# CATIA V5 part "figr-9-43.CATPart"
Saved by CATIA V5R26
Part number: Part1
Bounding box of the stored display mesh (mm): x -60 to 60, y -70.327 to 65.87, z 0 to 125
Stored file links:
  D:\_Deepak\CATIA\CATIA V5-6R2016_Deepak\Resources\Part files\Partfiles\c09_catia_v5_6r2016_prt\figr-9-43.CATPart
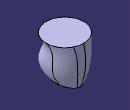
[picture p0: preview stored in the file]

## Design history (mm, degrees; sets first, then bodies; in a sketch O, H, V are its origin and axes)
Set1
  Plane1: type Offset, RefPlane xy-plane, Offset 125
Body1 (main body)
  Sketch1 on xy-plane, origin (0, 0, 0), H (1, 0, 0), V (0, 1, 0)
    ellipse A1 centre (0, 0) semi-axes 50, 30 rotation 270
    point P1 (30, 0)
    coincidence: P1 H, A1 P1
  Sketch2 on Plane1, origin (0, 0, 125), H (1, 0, 0), V (0, 1, 0)
    circle A1 centre (0, 0) radius 60
  Sketch3 on yz-plane, origin (0, 0, 0), H (0, 1, 0), V (0, 0, 1)
    arc A1 centre (-129.6632, 77.2731) radius 195.5761 from (50, 0) to (60, 125) ccw
    point P2 (50, 0)
    point P3 (60, 125)
    reference projected line E1 (-50, 0) -> (50, 0) from edge of Sketch1
    reference projected line E2 (-60, 125) -> (60, 125) from edge of Sketch2
    coincidence: P2 H, P2 E1, P3 E2
  Sketch4 on yz-plane, origin (0, 0, 0), H (0, 1, 0), V (0, 0, 1)
    spline S1 through (-50, 0) (-70, 40) (-50, 100) (-60, 125)
    reference projected line E1 (-60, 125) -> (60, 125) from edge of Sketch2
    reference projected line E2 (-50, 0) -> (50, 0) from edge of Sketch1
    point P1 (-60, 125)
    point P2 (-50, 0)
    coincidence: P1 E1, P2 E2
  Loft1: Sections (Sketch1; Sketch2), Guides (Sketch3; Sketch4)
